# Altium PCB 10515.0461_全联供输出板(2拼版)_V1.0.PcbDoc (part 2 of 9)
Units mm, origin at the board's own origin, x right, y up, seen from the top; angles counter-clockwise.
Board outline 283.88 x 134.8 mm, 2 copper layers (Top Layer, Bottom Layer); 298 components, 0 nets, 1264 pads, 970 vias.
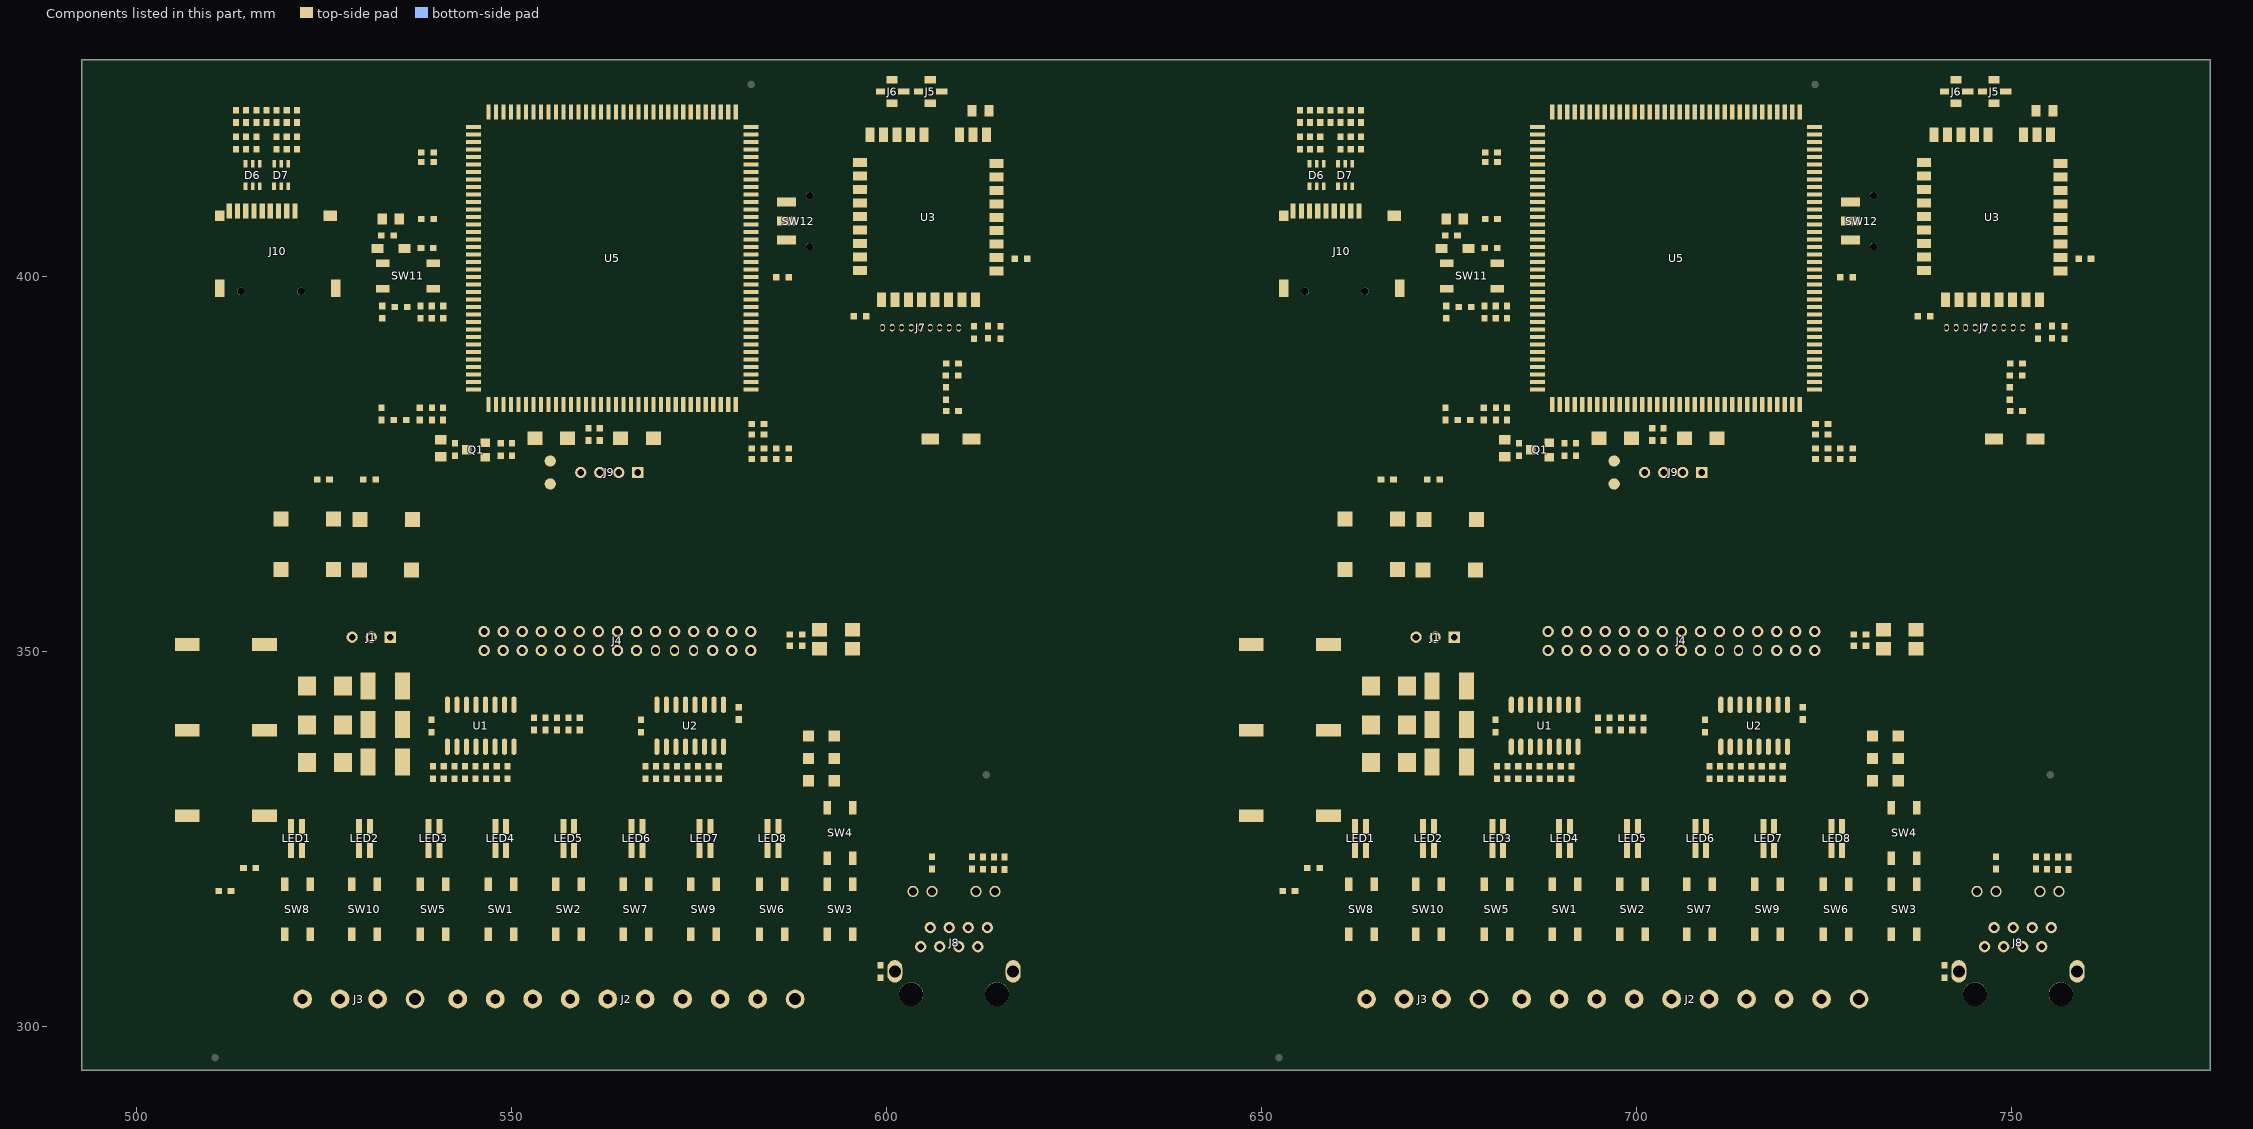
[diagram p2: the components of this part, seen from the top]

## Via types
v1: diameter 0.7, hole 0.4, Top Layer to Bottom Layer, tented both sides, 970 vias

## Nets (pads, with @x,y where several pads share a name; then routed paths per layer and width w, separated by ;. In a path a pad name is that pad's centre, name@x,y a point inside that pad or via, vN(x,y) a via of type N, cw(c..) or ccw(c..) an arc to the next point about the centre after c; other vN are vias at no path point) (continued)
copper on no net: (continued)
  Top Layer w0.3: 512.154,409.49 ccw(c511.813,409.831) 512.296,409.831 ccw(c512.779,409.831) 512.437,409.49 ; 512.296,408.698 512.296,414.58 512.699,414.983 514.482,414.983 v1@514.482,415.867 ; 513.026,418.822 ccw(c512.588,419.26) 513.207,419.26 ccw(c513.826,419.26) 513.388,418.822 ; 513.026,420.288 cw(c512.588,419.85) 513.207,419.85 cw(c513.826,419.85) 513.388,420.288 ; 513.026,422.378 ccw(c512.588,422.816) 513.207,422.816 ccw(c513.826,422.816) 513.388,422.378 ; v1@513.066,419.414 cw(c512.724,419.072) 513.207,419.072 cw(c513.69,419.072) v1@513.348,419.414 ; v1@513.066,419.696 ccw(c512.724,420.038) 513.207,420.038 ccw(c513.69,420.038) v1@513.348,419.696 ; 513.207,416.952 515.916,416.952 518.626,416.952 521.335,416.952 521.525,416.952 521.97,416.507 v1(521.97,410.538) ; 513.207,418.603 513.207,420.508 ; 513.207,422.159 513.207,425.143 v1(513.461,425.397) ; 513.207,424.301 cw(c514.557,424.301) v1@513.602,425.256 ; 513.207,425.025 cw(c513.833,425.025) v1@513.39,425.468 ; 513.258,409.49 ccw(c512.917,409.831) 513.4,409.831 ccw(c513.882,409.831) 513.541,409.49 ; 513.388,416.77 cw(c513.826,416.332) 513.826,416.952 cw(c513.826,417.571) 513.388,417.133 ; 513.4,408.698 513.4,413.398 513.842,413.84 516.128,413.84 516.382,414.094 516.382,414.983 v1@516.382,415.872 ; v1@514.209,412.81 cw(c513.561,412.162) 514.477,412.162 ; v1@514.214,415.726 cw(c513.566,415.078) 514.482,415.078 ; 514.356,409.49 ccw(c514.015,409.831) 514.498,409.831 ccw(c514.98,409.831) 514.639,409.49 ; 514.38,416.77 ccw(c513.943,416.332) 513.943,416.952 ccw(c513.943,417.571) 514.38,417.133 ; 514.38,418.822 ccw(c513.943,419.26) 514.562,419.26 ccw(c515.181,419.26) 514.743,418.822 ; 514.38,420.288 cw(c513.943,419.85) 514.562,419.85 cw(c515.181,419.85) 514.743,420.288 ; 514.38,422.378 ccw(c513.84,422.918) 514.604,422.918 ; 514.406,411.662 cw(c514.186,411.442) 514.498,411.442 ; v1@514.42,419.414 cw(c514.079,419.072) 514.562,419.072 cw(c515.045,419.072) v1@514.703,419.414 ; v1@514.42,419.696 ccw(c514.079,420.038) 514.562,420.038 ccw(c515.045,420.038) v1@514.703,419.696 ; 514.477,411.983 v1@514.477,412.951 ; 514.498,408.698 514.498,411.835 ; 514.562,418.603 514.562,420.508 ; 514.604,422.201 514.604,423.407 514.604,426.286 515.196,426.878 562.272,426.878 v1(562.737,426.413) ; 514.604,422.713 ccw(c515.078,422.713) 514.743,422.378 ; 514.743,416.77 cw(c515.181,416.332) 515.181,416.952 cw(c515.181,417.571) 514.743,417.133 ; v1@514.971,406.742 ccw(c513.465,408.248) 515.594,408.248 ; v1@515.183,406.53 ccw(c514.19,407.523) 515.594,407.523 ; v1@515.186,415.726 cw(c514.591,415.131) 515.432,415.131 ; 515.395,406.318 ccw(c514.914,406.799) 515.594,406.799 ; 515.432,411.983 515.432,410.853 515.681,410.604 ; 515.432,414.983 v1@515.432,415.811 ; 515.453,407.907 cw(c515.111,407.565) 515.594,407.565 cw(c516.077,407.565) 515.736,407.907 ; 515.594,406.601 515.594,408.698 515.594,409.548 ; 515.735,416.77 ccw(c515.297,416.332) 515.297,416.952 ccw(c515.297,417.571) 515.735,417.133 ; 515.735,418.822 ccw(c515.297,419.26) 515.916,419.26 ccw(c516.535,419.26) 516.098,418.822 ; 515.735,420.288 cw(c515.297,419.85) 515.916,419.85 cw(c516.535,419.85) 516.098,420.288 ; 515.735,422.378 ccw(c515.297,422.816) 515.916,422.816 ccw(c516.535,422.816) 516.098,422.378 ; v1@515.775,419.414 cw(c515.433,419.072) 515.916,419.072 cw(c516.399,419.072) v1@516.058,419.414 ; v1@515.775,419.696 ccw(c515.433,420.038) 515.916,420.038 ccw(c516.399,420.038) v1@516.058,419.696 ; v1@515.904,410.489 ccw(c515.681,410.332) 515.681,410.604 ; v1@515.904,410.719 cw(c515.681,410.876) 515.681,410.604 ; 515.916,418.603 515.916,420.508 ; 515.916,422.159 515.916,425.947 516.293,426.324 561.556,426.324 562.865,425.015 562.865,421.91 ; v1@515.94,410.604 515.681,410.604 ; 516.098,416.77 cw(c516.535,416.332) 516.535,416.952 cw(c516.535,417.571) 516.098,417.133 ; v1@516.158,415.726 cw(c515.616,415.184) 516.382,415.184 ; 516.382,411.983 516.946,411.983 ; 516.551,409.49 ccw(c515.596,410.444) 516.946,410.444 ; 516.763,409.277 ccw(c516.321,409.72) 516.946,409.72 ; 516.946,408.698 516.946,411.983 ; 517.09,420.288 cw(c516.652,419.85) 517.271,419.85 cw(c517.89,419.85) 517.452,420.288 ; 517.09,422.378 ccw(c516.652,422.816) 517.271,422.816 ccw(c517.89,422.816) 517.452,422.378 ; v1@517.13,415.726 cw(c516.788,415.384) 517.271,415.384 cw(c517.754,415.384) v1@517.412,415.726 ; v1@517.13,418.045 ccw(c516.788,418.387) 517.271,418.387 ccw(c517.754,418.387) v1@517.412,418.045 ; v1(517.144,425.397) 517.517,425.77 560.713,425.77 561.865,424.618 561.865,421.91 ; v1@517.144,425.597 ccw(c517.144,426.08) 517.485,425.738 ccw(c517.827,425.397) v1@517.344,425.397 ; v1@517.271,415.872 517.271,412.308 516.946,411.983 ; v1(517.271,417.904) 517.271,420.508 ; 517.271,422.159 517.271,423.492 518.033,424.254 559.484,424.254 559.865,423.873 559.865,421.91 ; 517.652,408.837 v1@517.652,410.538 ; 517.652,409.815 cw(c518.568,409.815) v1@517.92,410.463 ; 517.652,410.167 ccw(c518.61,410.167) 517.933,409.49 ; v1@518.146,413.699 cw(c517.804,413.357) 518.287,413.357 cw(c518.77,413.357) v1@518.428,413.699 ; 518.216,411.662 cw(c517.432,410.878) 518.541,410.878 ; v1(518.287,413.84) 518.287,411.983 518.541,411.729 518.541,410.157 518.891,409.807 ; 518.428,411.874 cw(c518.157,411.603) 518.541,411.603 ; 518.444,416.77 ccw(c518.007,416.332) 518.007,416.952 ccw(c518.007,417.571) 518.444,417.133 ; 518.444,418.822 ccw(c518.007,419.26) 518.626,419.26 ccw(c519.245,419.26) 518.807,418.822 ; 518.444,420.288 cw(c518.007,419.85) 518.626,419.85 cw(c519.245,419.85) 518.807,420.288 ; 518.444,422.378 ccw(c518.007,422.816) 518.626,422.816 ccw(c519.245,422.816) 518.807,422.378 ; v1@518.484,419.414 cw(c518.143,419.072) 518.626,419.072 cw(c519.109,419.072) v1@518.767,419.414 ; v1@518.484,419.696 ccw(c518.143,420.038) 518.626,420.038 ccw(c519.109,420.038) v1@518.767,419.696 ; v1@518.484,423.266 cw(c518.143,422.924) 518.626,422.924 cw(c519.109,422.924) v1@518.767,423.266 ; 518.626,418.603 518.626,420.508 ; 518.626,422.159 v1(518.626,423.407) ; 518.754,409.495 ccw(c518.463,409.807) 518.891,409.807 ; 518.774,409.924 cw(c518.246,409.397) 518.99,409.341 ; 518.807,416.77 cw(c519.245,416.332) 519.245,416.952 cw(c519.245,417.571) 518.807,417.133 ; 518.891,408.698 518.891,409.807 ; 519.027,409.495 cw(c519.318,409.807) 518.891,409.807 ; v1@519.035,413.346 ccw(c518.534,413.847) 519.242,413.847 ; v1(519.049,425.016) 560.197,425.016 560.865,424.348 560.865,421.91 ; v1@519.19,424.875 cw(c519.532,424.533) 519.532,425.016 cw(c519.532,425.499) v1@519.19,425.157 ; v1@519.242,410.604 519.242,411.983 ; 519.242,411.168 ccw(c519.933,411.168) v1@519.444,410.679 ; v1@519.242,413.271 519.242,414.983 ; 519.799,416.77 ccw(c519.361,416.332) 519.361,416.952 ccw(c519.361,417.571) 519.799,417.133 ; 519.799,418.822 ccw(c519.361,419.26) 519.98,419.26 ccw(c520.599,419.26) 520.162,418.822 ; 519.799,420.288 cw(c519.361,419.85) 519.98,419.85 cw(c520.599,419.85) 520.162,420.288 ; 519.799,422.378 ccw(c519.361,422.816) 519.98,422.816 ccw(c520.599,422.816) 520.162,422.378 ; v1@519.839,419.414 cw(c519.497,419.072) 519.98,419.072 cw(c520.463,419.072) v1@520.122,419.414 ; v1@519.839,419.696 ccw(c519.497,420.038) 519.98,420.038 ccw(c520.463,420.038) v1@520.122,419.696 ; v1@519.839,423.308 cw(c519.497,422.967) 519.98,422.967 cw(c520.463,422.967) v1@520.122,423.308 ; 519.846,409.488 ccw(c519.009,410.324) 520.192,410.324 ; 519.98,418.603 519.98,420.508 ; 519.98,422.159 v1(519.98,423.45) ; 519.987,408.696 519.987,409.444 520.192,409.649 520.192,411.983 v1(520.192,413.586) ; v1@520.051,413.445 cw(c519.709,413.103) 520.192,413.103 cw(c520.675,413.103) v1@520.333,413.445 ; v1@520.051,415.731 cw(c519.709,415.389) 520.192,415.389 cw(c520.675,415.389) v1@520.333,415.731 ; 520.162,416.77 cw(c520.599,416.332) 520.599,416.952 cw(c520.599,417.571) 520.162,417.133 ; 520.192,414.633 cw(c520.192,413.788) 520.789,414.386 ; v1(520.192,415.872) 520.192,414.983 521.087,414.088 521.087,408.698 ; 520.396,327.393 ccw(c519.969,327.82) 520.573,327.82 ccw(c521.177,327.82) 520.75,327.393 ; 520.573,326.235 520.573,330.782 521.265,331.474 539.172,331.474 539.496,331.798 539.496,333.005 ; v1(520.573,427.683) 520.692,427.564 562.729,427.564 563.865,426.428 563.865,421.91 ; v1@520.714,427.824 ccw(c521.343,428.453) 521.343,427.564 ; 520.945,409.49 ccw(c520.604,409.831) 521.087,409.831 ccw(c521.569,409.831) 521.228,409.49 ; 521.154,416.77 ccw(c520.716,416.332) 520.716,416.952 ccw(c520.716,417.571) 521.154,417.133 ; 521.154,418.822 ccw(c520.716,419.26) 521.335,419.26 ccw(c521.954,419.26) 521.516,418.822 ; 521.154,420.288 cw(c520.716,419.85) 521.335,419.85 cw(c521.954,419.85) 521.516,420.288 ; 521.154,422.378 ccw(c520.716,422.816) 521.335,422.816 ccw(c521.954,422.816) 521.516,422.378 ; v1@521.194,419.414 cw(c520.852,419.072) 521.335,419.072 cw(c521.818,419.072) v1@521.476,419.414 ; v1@521.194,419.696 ccw(c520.852,420.038) 521.335,420.038 ccw(c521.818,420.038) v1@521.476,419.696 ; v1@521.194,423.351 cw(c520.852,423.009) 521.335,423.009 cw(c521.818,423.009) v1@521.476,423.351 ; 521.335,418.603 521.335,420.508 ; 521.335,422.159 v1(521.335,423.492) ; v1@521.829,410.679 ccw(c521.487,411.021) 521.97,411.021 ccw(c522.453,411.021) v1@522.111,410.679 ; 521.856,327.368 ccw(c521.429,327.795) 522.033,327.795 ccw(c522.637,327.795) 522.21,327.368 ; v1(521.97,428.318) 563.499,428.318 564.865,426.952 564.865,421.91 ; 522.033,326.21 522.033,330.21 522.743,330.92 540.65,330.92 540.911,331.181 540.911,333.005 ; 523.086,312.243 v1(526.923,312.243) ; 523.333,311.995 cw(c523.931,311.398) 523.931,312.243 cw(c523.931,313.088) 523.333,312.49 ; v1@526.782,312.101 ccw(c526.44,311.76) 526.44,312.243 ccw(c526.44,312.726) v1@526.782,312.384 ; 528.125,309.192 528.633,309.7 ; 528.385,311.595 cw(c527.788,310.998) 528.633,310.998 cw(c529.478,310.998) 528.88,311.595 ; 528.385,319.59 ccw(c527.788,320.188) 528.633,320.188 ccw(c529.478,320.188) 528.88,319.59 ; v1@528.492,320.286 cw(c528.15,319.944) 528.633,319.944 cw(c529.116,319.944) v1@528.774,320.286 ; 528.633,309.26 528.633,309.7 ; 528.633,312.243 528.633,309.7 ; 528.633,318.943 v1(528.633,320.427) ; 529.082,309.251 528.633,309.7 ; 529.468,327.393 ccw(c529.041,327.82) 529.644,327.82 ccw(c530.248,327.82) 529.821,327.393 ; 529.644,326.235 529.644,329.82 530.19,330.366 542.001,330.366 542.326,330.691 542.326,333.005 ; 530.928,327.368 ccw(c530.501,327.795) 531.104,327.795 ccw(c531.708,327.795) 531.281,327.368 ; 531.104,326.21 531.104,329.248 531.668,329.812 543.352,329.812 543.741,330.201 543.741,333.005 ; 531.785,319.59 ccw(c531.188,320.188) 532.033,320.188 ccw(c532.878,320.188) 532.28,319.59 ; 532.033,318.943 532.033,321.541 532.476,321.984 550.129,321.984 550.488,322.343 550.488,334.916 551.688,336.116 561.086,336.116 561.459,336.489 561.459,346.608 561.546,346.695 561.546,350.086 ; v1(533.146,321.003) 533.573,321.43 550.358,321.43 551.042,322.114 551.042,334.2 552.069,335.227 561.467,335.227 562.013,335.773 562.013,346.378 562.864,347.229 562.864,351.404 564.086,352.626 ; v1@533.146,321.203 ccw(c533.146,321.686) 533.487,321.344 ccw(c533.829,321.003) v1@533.346,321.003 ; v1(533.4,312.243) 537.783,312.243 ; v1@533.541,312.101 cw(c533.883,311.76) 533.883,312.243 cw(c533.883,312.726) v1@533.541,312.384 ; 537.536,311.995 ccw(c536.938,311.398) 536.938,312.243 ccw(c536.938,313.088) 537.536,312.49 ; 537.689,403.938 ccw(c537.251,404.376) 537.87,404.376 ccw(c538.489,404.376) 538.052,403.938 ; 537.727,415.056 cw(c537.289,414.618) 537.909,414.618 cw(c538.528,414.618) 538.09,415.056 ; 537.727,415.418 ccw(c537.289,415.856) 537.909,415.856 ccw(c538.528,415.856) 538.09,415.418 ; 537.727,416.326 cw(c537.289,415.888) 537.909,415.888 cw(c538.528,415.888) 538.09,416.326 ; 537.783,319.544 539.115,320.876 550.672,320.876 551.596,321.8 551.596,333.484 552.577,334.465 561.848,334.465 562.567,335.184 562.567,346.149 564.086,347.668 564.086,350.086 ; 537.783,319.693 ccw(c537.783,320.051) 538.037,319.798 ; 537.87,403.757 537.87,405.61 538.17,405.91 544.865,405.91 ; 537.909,416.507 537.909,414.158 538.226,413.84 540.766,413.84 541.836,414.91 544.865,414.91 546.427,414.91 546.735,414.602 546.735,385.91 ; 538.133,319.343 cw(c539.465,319.343) 538.523,320.284 ; 538.716,326.616 538.716,328.859 539.115,329.258 544.703,329.258 545.157,329.712 545.157,333.005 ; 538.716,328.17 ccw(c539.815,328.17) 539.038,327.393 ; 539.315,332.785 cw(c538.877,332.347) 539.496,332.347 cw(c540.115,332.347) 539.677,332.785 ; 539.336,334.894 ccw(c539.069,335.227) 539.496,335.227 ; 539.34,403.938 ccw(c538.902,404.376) 539.521,404.376 ccw(c540.14,404.376) 539.703,403.938 ; 539.452,334.694 cw(c540.635,334.694) 539.799,335.53 ; 539.496,334.656 539.496,335.227 ; 539.521,403.757 539.521,404.467 539.964,404.91 544.865,404.91 546.648,404.91 ; 539.559,407.617 540.267,406.91 544.865,406.91 ; 539.559,415.237 540.639,415.237 541.312,415.91 544.865,415.91 ; 539.559,416.507 539.962,416.91 544.865,416.91 ; 539.567,416.538 cw(c540.465,415.639) 540.465,416.91 ; 539.598,407.361 cw(c539.598,406.834) 539.97,407.206 ; 539.656,334.894 cw(c539.923,335.227) 539.496,335.227 ; 539.752,334.694 cw(c541.659,334.694) 540.311,336.042 ; 539.779,415.056 cw(c540.217,414.618) 540.217,415.237 cw(c540.217,415.856) 539.779,415.418 ; 539.779,416.326 cw(c541.19,414.915) 541.19,416.91 ; 539.854,407.617 ccw(c540.565,407.617) 540.062,407.114 ; 540.176,326.591 540.176,328.287 540.512,328.623 546.1,328.623 546.572,329.095 546.572,333.005 ; 540.176,328.145 ccw(c541.275,328.145) 540.498,327.368 ; 540.73,332.785 cw(c540.292,332.347) 540.911,332.347 cw(c541.53,332.347) 541.092,332.785 ; 540.73,334.875 ccw(c539.11,336.495) 541.401,336.495 ; 540.911,334.656 541.401,335.145 ; 540.916,334.95 ccw(c540.929,335.617) 541.401,335.145 ; 540.942,334.663 ccw(c539.834,335.771) 541.401,335.771 ; 541.154,334.451 ccw(c540.558,335.047) 541.401,335.047 ; 541.168,334.694 cw(c541.695,334.694) 541.322,335.066 ; 541.183,312.243 546.832,312.243 ; 541.26,336.368 cw(c540.918,336.026) 541.401,336.026 cw(c541.884,336.026) 541.542,336.368 ; 541.401,337.259 541.401,335.145 ; 541.431,311.995 cw(c542.028,311.398) 542.028,312.243 cw(c542.028,313.088) 541.431,312.49 ; 542.145,332.785 cw(c541.707,332.347) 542.326,332.347 cw(c542.945,332.347) 542.508,332.785 ; 542.145,334.875 ccw(c540.875,336.145) 542.671,336.145 ; 542.326,334.656 542.671,335 542.671,337.259 ; 542.357,334.663 ccw(c541.599,335.421) 542.671,335.421 ; 542.53,336.368 cw(c542.188,336.026) 542.671,336.026 cw(c543.154,336.026) 542.812,336.368 ; 542.53,341.956 cw(c542.188,341.614) 542.671,341.614 cw(c543.154,341.614) 542.812,341.956 ; 542.671,342.847 542.671,340.561 540.385,338.275 540.385,336.116 539.496,335.227 ; 543.56,332.785 cw(c543.122,332.347) 543.741,332.347 cw(c544.36,332.347) 543.923,332.785 ; 543.56,334.875 ccw(c542.641,335.794) 543.941,335.794 ; 543.772,334.663 ccw(c543.365,335.07) 543.941,335.07 ; 543.8,336.368 cw(c543.458,336.026) 543.941,336.026 cw(c544.424,336.026) 544.082,336.368 ; 543.941,334.855 543.941,337.259 ; 544.052,404.822 ccw(c543.838,404.608) 543.838,404.91 ccw(c543.838,405.212) 544.052,404.998 ; 544.052,405.822 ccw(c543.838,405.608) 543.838,405.91 ccw(c543.838,406.212) 544.052,405.998 ; 544.052,406.822 ccw(c543.838,406.608) 543.838,406.91 ccw(c543.838,407.212) 544.052,406.998 ; 544.052,414.822 ccw(c543.838,414.608) 543.838,414.91 ccw(c543.838,415.212) 544.052,414.998 ; 544.052,415.822 ccw(c543.838,415.608) 543.838,415.91 ccw(c543.838,416.212) 544.052,415.998 ; 544.052,416.822 ccw(c543.838,416.608) 543.838,416.91 ccw(c543.838,417.212) 544.052,416.998 ; v1@544.576,382.471 544.576,383.36 ; 544.576,383.233 544.576,383.36 ; 544.576,383.911 cw(c545.864,383.911) 544.953,384.822 ccw(c545.167,384.608) 544.865,384.608 ccw(c544.563,384.608) 544.777,384.822 ; 544.576,384.635 cw(c545.14,384.635) 544.741,385.034 ; 544.636,384.69 cw(c544.865,384.461) 544.865,384.785 ; v1@544.647,382.527 ccw(c544.12,383.054) 544.865,383.054 ; 544.658,384.712 ccw(c544.46,384.91) 544.74,384.91 ; v1@544.703,382.471 544.865,382.633 544.865,384.91 ; v1@544.717,382.739 cw(c545.059,383.081) 544.576,383.081 cw(c544.093,383.081) 544.435,382.739 ccw(c543.395,383.779) 544.865,383.779 ; 544.865,385.91 546.735,385.91 ; 544.865,388.91 546.697,388.91 ; 544.865,391.91 546.694,391.91 ; 544.865,394.91 546.728,394.91 ; 544.865,397.91 546.663,397.91 ; 544.975,332.785 cw(c544.538,332.347) 545.157,332.347 cw(c545.776,332.347) 545.338,332.785 ; 544.975,334.875 ccw(c544.406,335.444) 545.211,335.444 ; 545.07,336.368 cw(c544.728,336.026) 545.211,336.026 cw(c545.694,336.026) 545.352,336.368 ; 545.211,334.71 545.211,337.259 ; 545.211,335.181 ccw(c545.644,335.181) 545.338,334.875 ; 545.678,384.822 cw(c545.892,384.608) 545.892,384.91 cw(c545.892,385.212) 545.678,384.998 ; 545.678,385.822 cw(c545.892,385.608) 545.892,385.91 cw(c545.892,386.212) 545.678,385.998 ; 545.678,388.822 cw(c545.892,388.608) 545.892,388.91 cw(c545.892,389.212) 545.678,388.998 ; 545.678,391.822 cw(c545.892,391.608) 545.892,391.91 cw(c545.892,392.212) 545.678,391.998 ; 545.678,394.822 cw(c545.892,394.608) 545.892,394.91 cw(c545.892,395.212) 545.678,394.998 ; 545.678,397.822 cw(c545.892,397.608) 545.892,397.91 cw(c545.892,398.212) 545.678,397.998 ; 545.678,404.822 cw(c545.892,404.608) 545.892,404.91 cw(c545.892,405.212) 545.678,404.998 ; 545.678,414.822 cw(c545.892,414.608) 545.892,414.91 cw(c545.892,415.212) 545.678,414.998 ; 546.34,336.368 cw(c545.998,336.026) 546.481,336.026 cw(c546.964,336.026) 546.622,336.368 ; 546.34,343.738 ccw(c545.998,344.08) 546.481,344.08 ccw(c546.964,344.08) 546.622,343.738 ; v1@546.34,344.23 cw(c545.998,343.888) 546.481,343.888 cw(c546.964,343.888) v1@546.622,344.23 ; 546.354,380.82 546.862,381.328 546.862,381.455 ; 546.39,332.785 cw(c545.953,332.347) 546.572,332.347 cw(c547.191,332.347) 546.753,332.785 ; 546.39,334.875 ccw(c546.172,335.094) 546.481,335.094 ; 546.481,334.746 546.481,337.259 ; 546.481,335.532 ccw(c547.41,335.532) 546.753,334.875 ; 546.481,342.847 v1(546.481,344.371) ; 546.585,311.995 ccw(c545.987,311.398) 545.987,312.243 ccw(c545.987,313.088) 546.585,312.49 ; 546.777,382.097 cw(c546.57,381.89) 546.862,381.89 ; 546.832,318.943 546.832,319.322 547.832,320.322 551.007,320.322 552.15,321.465 552.15,333.149 552.577,333.576 556.26,333.576 561.975,333.576 563.121,334.722 563.121,345.919 565.252,348.05 565.252,351.252 566.626,352.626 ; 546.832,319.693 ccw(c546.832,320.588) 547.465,319.955 ; 546.862,381.201 546.862,381.455 ; 546.862,381.876 cw(c547.174,381.876) 546.953,382.097 ; 546.865,382.91 546.862,382.907 546.862,381.455 ; 546.875,381.214 547.865,381.214 ; 547.182,319.343 cw(c547.977,319.343) 547.415,319.905 ; 547.611,327.393 ccw(c546.702,328.301) 547.987,328.301 ; 547.61,336.368 cw(c547.268,336.026) 547.751,336.026 cw(c548.234,336.026) 547.892,336.368 ; 547.61,343.738 ccw(c547.268,344.08) 547.751,344.08 ccw(c548.234,344.08) 547.892,343.738 ; 547.751,334.891 547.751,337.259 ; 547.751,335.158 ccw(c548.451,335.158) 547.956,334.663 ; 547.751,335.882 ccw(c549.175,335.882) 548.168,334.875 ; 547.751,342.847 547.751,344.752 v1(548.259,345.26) ; 547.787,327.317 547.787,326.616 547.987,326.816 547.987,333.005 ; 547.806,332.785 cw(c547.368,332.347) 547.987,332.347 cw(c548.606,332.347) 548.168,332.785 ; 547.823,327.181 ccw(c547.426,327.577) 547.987,327.577 ; 547.865,380.82 547.963,380.722 548.865,380.722 548.865,382.91 ; v1@548.059,345.26 cw(c547.576,345.26) 547.918,344.919 cw(c548.259,344.577) v1@548.259,345.06 ; v1@548.626,385.769 ccw(c548.284,385.427) 548.284,385.91 ccw(c548.284,386.393) v1@548.626,386.051 ; 548.777,382.097 cw(c548.563,381.883) 548.865,381.883 cw(c549.167,381.883) 548.953,382.097 ; 548.88,336.368 cw(c548.538,336.026) 549.021,336.026 cw(c549.504,336.026) 549.162,336.368 ; v1@548.908,385.769 cw(c549.25,385.427) 549.25,385.91 cw(c549.25,386.393) v1@548.908,386.051 ; 549.021,335.036 549.021,337.259 ; 549.021,335.508 ccw(c550.217,335.508) 549.371,334.663 ; 549.021,336.232 ccw(c550.941,336.232) 549.583,334.875 ; 549.071,327.368 ccw(c548.27,328.168) 549.402,328.168 ; 549.221,332.785 cw(c548.783,332.347) 549.402,332.347 cw(c550.021,332.347) 549.583,332.785 ; 549.247,327.254 549.247,326.591 549.402,326.746 549.402,333.005 ; 550.232,312.243 555.881,312.243 555.881,311.73 ; 550.232,318.531 552.704,321.003 552.704,332.433 553.085,332.814 562.483,332.814 563.675,334.006 563.675,345.69 566.626,348.641 566.626,350.086 ; 550.48,311.995 cw(c551.077,311.398) 551.077,312.243 cw(c551.077,313.088) 550.48,312.49 ; v1@551.547,313.143 ccw(c551.205,313.485) 551.688,313.485 ccw(c552.171,313.485) v1@551.829,313.143 ; v1(551.688,313.002) 551.688,319.204 553.258,320.774 553.258,331.463 553.855,332.06 563.126,332.06 564.229,333.163 564.229,345.461 567.817,349.049 567.817,353.515 567.428,353.904 562.618,353.904 ; v1@552.436,313.651 ccw(c552.094,313.993) 552.577,313.993 ccw(c553.06,313.993) v1@552.718,313.651 ; v1@552.577,313.637 552.577,319.309 553.863,320.595 553.863,330.925 554.444,331.506 563.588,331.506 564.783,332.701 564.783,345.231 567.398,347.846 571.292,347.846 571.706,348.26 571.706,350.086 ; 552.777,339.262 cw(c552.339,338.824) 552.958,338.824 cw(c553.577,338.824) 553.139,339.262 ; 552.958,336.116 552.958,339.482 ; 553.06,378.407 553.06,378.661 ; v1@553.452,313.143 ccw(c553.11,313.485) 553.593,313.485 ccw(c554.076,313.485) v1@553.734,313.143 ; v1@553.452,385.769 ccw(c553.11,385.427) 553.11,385.91 ccw(c553.11,386.393) v1@553.452,386.051 ; v1(553.593,313.002) 553.593,319.542 554.482,320.431 554.482,330.346 555.088,330.952 564.05,330.952 565.337,332.239 565.337,345.002 567.627,347.292 577.469,347.292 578.104,347.927 578.104,351.308 576.786,352.626 ; v1@553.734,385.769 cw(c554.076,385.427) 554.076,385.91 cw(c554.076,386.393) v1@553.734,386.051 ; 554.301,339.262 cw(c553.863,338.824) 554.482,338.824 cw(c555.101,338.824) 554.663,339.262 ; v1@554.341,313.651 ccw(c553.999,313.993) 554.482,313.993 ccw(c554.965,313.993) v1@554.623,313.651 ; v1@554.341,335.086 ccw(c553.999,334.744) 553.999,335.227 ccw(c553.999,335.71) v1@554.341,335.368 ; v1@554.341,338.416 ccw(c553.999,338.758) 554.482,338.758 ccw(c554.965,338.758) v1@554.623,338.416 ; v1@554.482,313.637 554.482,319.606 555.102,320.226 555.102,329.57 555.93,330.398 564.893,330.398 565.891,331.396 565.891,344.772 567.857,346.738 578.439,346.738 579.326,347.625 579.326,350.086 ; v1(554.482,338.275) 554.482,339.482 ; v1@554.623,335.086 cw(c554.965,334.744) 554.965,335.227 cw(c554.965,335.71) v1@554.623,335.368 ; 555.117,372.438 561.467,372.438 561.721,372.692 ; 555.117,375.359 556.895,375.359 557.428,375.892 557.428,378.09 ; 555.329,372.099 cw(c556.148,371.28) 556.148,372.438 ; 555.541,371.887 cw(c556.872,370.556) 556.872,372.438 ; 555.541,372.735 ccw(c556.259,373.453) 556.259,372.438 ; 555.541,374.935 cw(c556.566,373.91) 556.566,375.359 cw(c556.566,376.808) 555.541,375.783 ; 555.633,311.995 ccw(c555.036,311.398) 555.036,312.243 ccw(c555.036,313.088) 555.633,312.49 ; 555.825,339.262 cw(c555.387,338.824) 556.006,338.824 cw(c556.625,338.824) 556.187,339.262 ; v1@555.865,334.324 ccw(c555.523,333.982) 555.523,334.465 ccw(c555.523,334.948) v1@555.865,334.606 ; v1@555.865,338.416 ccw(c555.523,338.758) 556.006,338.758 ccw(c556.489,338.758) v1@556.147,338.416 ; 555.881,318.943 555.881,319.35 ; v1(556.006,338.275) 556.006,339.482 ; v1@556.147,334.324 cw(c556.489,333.982) 556.489,334.465 cw(c556.489,334.948) v1@556.147,334.606 ; 556.466,352.626 559.006,352.626 ; 556.682,327.393 ccw(c556.255,327.82) 556.859,327.82 ccw(c557.462,327.82) 557.035,327.393 ; 556.725,385.91 ccw(c556.725,386.489) v1@557.135,386.08 ; 556.859,326.235 556.859,326.616 556.859,329.603 557.1,329.844 566.879,329.844 567.817,330.782 567.817,333.005 ; 556.861,385.91 cw(c556.861,385.523) v1@557.135,385.797 ; v1(556.895,314.272) 558.8,314.272 ; 556.898,377.877 cw(c555.617,376.596) 557.428,376.596 cw(c559.239,376.596) 557.958,377.877 ; 556.899,352.193 cw(c557.943,351.149) 557.943,352.626 cw(c557.943,354.104) 556.899,353.059 ; v1@557.036,314.131 cw(c557.378,313.789) 557.378,314.272 cw(c557.378,314.755) v1@557.036,314.413 ; 557.11,378.089 cw(c556.342,377.321) 557.428,377.321 cw(c558.514,377.321) 557.746,378.089 ; 557.349,339.262 cw(c556.911,338.824) 557.53,338.824 cw(c558.149,338.824) 557.711,339.262 ; v1@557.389,333.435 ccw(c557.047,333.093) 557.047,333.576 ccw(c557.047,334.059) v1@557.389,333.717 ; v1@557.389,338.416 ccw(c557.047,338.758) 557.53,338.758 ccw(c558.013,338.758) v1@557.671,338.416 ; v1@557.417,385.797 cw(c557.691,385.523) 557.691,385.91 ; v1@557.417,386.08 ccw(c557.827,386.489) 557.827,385.91 ; v1(557.53,338.275) 557.53,339.482 ; v1@557.671,333.435 cw(c558.013,333.093) 558.013,333.576 cw(c558.013,334.059) v1@557.671,333.717 ; 558.142,327.368 ccw(c557.715,327.795) 558.319,327.795 ccw(c558.922,327.795) 558.495,327.368 ; 558.319,326.21 558.319,326.591 558.319,329.071 558.538,329.29 568.484,329.29 569.214,330.02 569.214,333.005 ; 558.573,352.193 ccw(c557.528,351.149) 557.528,352.626 ccw(c557.528,354.104) 558.573,353.059 ; 558.777,421.097 cw(c558.563,420.883) 558.865,420.883 cw(c559.167,420.883) 558.953,421.097 ; 558.865,421.91 558.865,418.347 559.302,417.91 577.865,417.91 ; 558.873,339.262 cw(c558.435,338.824) 559.054,338.824 cw(c559.673,338.824) 559.235,339.262 ; v1@558.913,332.673 ccw(c558.571,332.331) 558.571,332.814 ccw(c558.571,333.297) v1@558.913,332.955 ; v1@558.913,338.416 ccw(c558.571,338.758) 559.054,338.758 ccw(c559.537,338.758) v1@559.195,338.416 ; v1(559.054,338.275) 559.054,339.482 ; v1@559.195,332.673 cw(c559.537,332.331) 559.537,332.814 cw(c559.537,333.297) v1@559.195,332.955 ; 559.281,313.891 558.9,314.272 ; 559.281,314.272 558.8,314.272 ; 559.281,314.653 558.9,314.272 ; 559.281,318.943 559.281,319.325 560.36,320.404 572.861,320.404 573.877,319.388 573.877,318.943 ; 559.281,319.693 ccw(c559.281,320.581) 559.909,319.953 ; 559.631,319.343 cw(c560.432,319.343) 559.866,319.91 ; 559.777,383.723 ccw(c559.563,383.937) 559.865,383.937 ccw(c560.167,383.937) 559.953,383.723 ; 559.777,422.723 ccw(c559.563,422.937) 559.865,422.937 ccw(c560.167,422.937) 559.953,422.723 ; 559.79,384.91 544.865,384.91 ; 559.865,382.91 559.865,385.861 ; 560.016,377.87 cw(c559.578,377.432) 560.197,377.432 cw(c560.816,377.432) 560.378,377.87 ; 560.197,375.994 560.197,378.09 ; 560.197,379.741 560.865,380.409 560.865,382.91 ; 560.197,380.035 ccw(c560.197,380.746) 560.7,380.243 ; 560.453,379.779 cw(c560.98,379.779) 560.608,380.151 ; 560.777,382.097 cw(c560.563,381.883) 560.865,381.883 cw(c561.167,381.883) 560.953,382.097 ; 560.777,422.723 ccw(c560.563,422.937) 560.865,422.937 ccw(c561.167,422.937) 560.953,422.723 ; 561.113,349.653 cw(c560.068,348.609) 561.546,348.609 cw(c563.023,348.609) 561.979,349.653 ; 561.38,373.341 cw(c560.932,372.692) 561.721,372.692 ; 561.54,377.87 cw(c561.102,377.432) 561.721,377.432 cw(c562.34,377.432) 561.902,377.87 ; 561.54,379.96 ccw(c560.754,380.745) 561.865,380.745 ; 561.546,352.626 561.546,352.832 562.618,353.904 ; 561.546,353.238 ccw(c561.546,354.218) 562.239,353.525 ; 561.777,382.097 cw(c561.563,381.883) 561.865,381.883 cw(c562.167,381.883) 561.953,382.097 ; 561.777,422.723 ccw(c561.563,422.937) 561.865,422.937 ccw(c562.167,422.937) 561.953,422.723 ; 561.813,378.09 ccw(c561.813,380.984) 563.86,378.937 ; 561.857,352.648 cw(c562.872,352.719) 562.153,353.439 ; 561.865,379.885 561.865,382.91 ; 561.902,377.908 cw(c562.34,377.47) 562.34,378.09 cw(c562.34,378.709) 561.902,378.271 ; 562.062,373.341 ccw(c562.51,372.692) 561.721,372.692 ; 562.156,352.669 cw(c563.741,352.78) 562.618,353.904 ; 562.537,378.09 ccw(c562.537,380.26) 564.072,378.725 ; v1@562.537,426.413 ccw(c562.054,426.413) 562.396,426.754 ccw(c562.737,427.096) v1@562.737,426.613 ; v1@562.724,384.742 cw(c562.382,384.4) 562.865,384.4 cw(c563.348,384.4) v1@563.006,384.742 ; 562.777,303.604 562.777,308.095 563.245,308.563 590.429,308.563 592.455,310.589 596.265,310.589 596.9,311.224 596.9,330.909 596.392,331.417 589.915,331.417 589.56,331.772 ; 562.777,383.723 ccw(c562.563,383.937) 562.865,383.937 ccw(c563.167,383.937) 562.953,383.723 ; 562.777,422.723 ccw(c562.563,422.937) 562.865,422.937 ccw(c563.167,422.937) 562.953,422.723 ; 562.865,382.91 v1(562.865,384.883) ; 563.261,378.09 ccw(c563.261,379.536) 564.284,378.513 ; 563.346,378.09 cw(c563.346,377.363) 563.86,377.877 ; 563.474,352.626 cw(c561.996,352.626) 563.041,351.581 cw(c564.086,350.536) 564.086,352.014 ; 563.653,349.653 cw(c562.608,348.609) 564.086,348.609 cw(c565.563,348.609) 564.519,349.653 ; 563.777,422.723 ccw(c563.563,422.937) 563.865,422.937 ccw(c564.167,422.937) 563.953,422.723 ; 564.172,378.09 561.721,378.09 561.721,373.835 561.721,372.692 ; 564.777,382.097 cw(c564.563,381.883) 564.865,381.883 cw(c565.167,381.883) 564.953,382.097 ; 564.777,422.723 ccw(c564.563,422.937) 564.865,422.937 ccw(c565.167,422.937) 564.953,422.723 ; 564.865,382.91 564.865,380.724 565.785,379.804 571.5,379.804 571.881,379.423 571.881,376.248 572.516,375.613 581.977,375.613 ; 565.753,327.393 ccw(c565.327,327.82) 565.93,327.82 ccw(c566.534,327.82) 566.107,327.393 ; 565.777,382.097 cw(c565.563,381.883) 565.865,381.883 cw(c566.167,381.883) 565.953,382.097 ; 565.777,421.097 cw(c565.563,420.883) 565.865,420.883 cw(c566.167,420.883) 565.953,421.097 ; 565.865,382.91 565.865,381.248 566.547,380.566 572.135,380.566 572.516,380.185 572.516,377.518 573.024,377.01 581.977,377.01 ; 565.865,417.99 565.865,421.91 ; 565.93,326.235 565.93,326.616 565.93,328.26 566.293,328.623 569.722,328.623 570.611,329.512 570.611,333.005 ; 565.966,417.91 ccw(c565.966,418.806) v1@566.6,418.172 ; 566.014,352.626 cw(c564.536,352.626) 565.581,351.581 cw(c566.626,350.536) 566.626,352.014 ; 566.2,349.646 cw(c565.226,348.641) 566.626,348.641 cw(c568.026,348.641) 567.052,349.646 ; 566.777,382.097 cw(c566.563,381.883) 566.865,381.883 cw(c567.167,381.883) 566.953,382.097 ; 566.865,382.91 566.865,381.518 567.182,381.201 573.024,381.201 573.278,380.947 573.278,378.28 573.659,377.899 v1(587.883,377.899) ; v1@566.883,418.172 ccw(c567.516,418.806) 567.516,417.91 ; 566.999,304.382 ccw(c565.121,306.26) 567.777,306.26 ccw(c570.433,306.26) 568.555,304.382 ; 567.211,304.17 ccw(c565.846,305.535) 567.777,305.535 ccw(c569.708,305.535) 568.343,304.17 ; 567.241,327.392 ccw(c567.021,327.688) 567.39,327.688 ; 567.344,327.171 cw(c567.832,327.38) 567.457,327.755 ; 567.39,326.21 567.39,326.591 567.39,327.688 ; 567.539,327.392 cw(c567.759,327.688) 567.39,327.688 ; 567.596,385.91 ccw(c567.596,388.093) v1@569.14,386.549 ; 567.62,327.289 cw(c568.273,327.567) 567.771,328.069 ; 567.636,332.785 cw(c567.198,332.347) 567.817,332.347 cw(c568.436,332.347) 567.998,332.785 ; 567.636,334.875 ccw(c566.278,336.232) 568.198,336.232 ; 567.777,303.604 567.777,307.715 568.071,308.009 590.658,308.009 592.684,310.035 596.494,310.035 597.454,310.995 597.454,332.154 596.896,332.712 592.989,332.712 ; 567.817,334.656 568.198,335.037 568.198,338.021 570.611,340.434 570.611,342.847 ; 567.848,334.663 ccw(c567.002,335.508) 568.198,335.508 ; 568.32,385.91 ccw(c568.32,387.369) v1@569.352,386.337 ; 568.777,383.723 ccw(c568.563,383.937) 568.865,383.937 ccw(c569.167,383.937) 568.953,383.723 ; 568.865,382.91 568.865,385.815 ; 568.998,386.125 ccw(c569.518,386.645) 569.518,385.91 ; 569.033,332.785 cw(c568.595,332.347) 569.214,332.347 cw(c569.833,332.347) 569.395,332.785 ; 569.033,334.875 ccw(c568.288,335.619) 569.341,335.619 ; 569.045,385.91 ccw(c569.045,386.645) 569.564,386.125 ; 569.2,336.368 cw(c568.858,336.026) 569.341,336.026 cw(c569.824,336.026) 569.482,336.368 ; v1@569.21,386.337 ccw(c570.242,387.369) 570.242,385.91 ; 569.341,334.783 569.341,337.259 ; v1@569.423,386.549 ccw(c570.966,388.093) 570.966,385.91 ; 570.43,332.785 cw(c569.992,332.347) 570.611,332.347 cw(c571.23,332.347) 570.792,332.785 ; 570.43,334.875 ccw(c569.992,335.313) 570.611,335.313 ccw(c571.23,335.313) 570.792,334.875 ; 570.47,336.368 cw(c570.128,336.026) 570.611,336.026 cw(c571.094,336.026) 570.752,336.368 ; 570.47,341.956 cw(c570.128,341.614) 570.611,341.614 cw(c571.094,341.614) 570.752,341.956 ; 570.611,334.656 570.611,337.259 ; 571.388,349.606 cw(c570.62,348.838) 571.706,348.838 cw(c572.792,348.838) 572.024,349.606 ; 571.74,336.368 cw(c571.398,336.026) 571.881,336.026 cw(c572.364,336.026) 572.022,336.368 ; 571.74,343.738 ccw(c571.398,344.08) 571.881,344.08 ccw(c572.364,344.08) 572.022,343.738 ; 571.827,332.785 cw(c571.389,332.347) 572.008,332.347 cw(c572.627,332.347) 572.189,332.785 ; 571.881,334.783 571.881,337.259 ; 571.881,335.619 ccw(c572.934,335.619) 572.189,334.875 ; 571.881,342.847 571.881,345.768 572.262,346.149 581.406,346.149 581.866,346.609 581.866,350.086 ; 572.008,333.005 572.008,328.623 571.454,328.069 567.771,328.069 ; 572.777,303.604 572.777,306.954 573.278,307.455 590.888,307.455 592.914,309.481 596.724,309.481 598.008,310.765 598.008,333.957 597.627,334.338 590.169,334.338 589.56,334.947 589.56,335.697 ; v1@572.883,354.136 cw(c572.541,353.794) 573.024,353.794 cw(c573.507,353.794) v1@573.165,354.136 ; v1@572.883,354.418 ccw(c572.541,354.76) 573.024,354.76 ccw(c573.507,354.76) v1@573.165,354.418 ; v1@572.883,354.771 cw(c572.541,354.429) 573.024,354.429 cw(c573.507,354.429) v1@573.165,354.771 ; 573.01,336.368 cw(c572.668,336.026) 573.151,336.026 cw(c573.634,336.026) 573.292,336.368 ; v1(573.024,354.912) 573.024,351.308 574.246,350.086 ; 573.151,334.91 573.151,337.259 ; 573.151,335.202 ccw(c573.913,335.202) 573.374,334.663 ; 573.151,335.926 ccw(c574.637,335.926) 573.586,334.875 ; 573.201,351.131 ccw(c574.246,352.176) 574.246,350.698 ; 573.224,332.785 cw(c572.786,332.347) 573.405,332.347 cw(c574.024,332.347) 573.586,332.785 ; 573.247,320.018 cw(c572.572,319.343) 573.527,319.343 ; 573.357,319.908 ccw(c573.877,320.428) 573.877,319.693 ; 573.405,333.005 573.405,328.496 573.849,328.052 574.865,328.052 575.002,327.915 575.002,326.616 ; 573.592,350.74 cw(c573.101,350.248) 573.796,350.248 ; 573.713,350.619 ccw(c574.246,351.151) 574.246,350.398 ; 573.777,382.097 cw(c573.563,381.883) 573.865,381.883 cw(c574.167,381.883) 573.953,382.097 ; 573.777,421.097 cw(c573.563,420.883) 573.865,420.883 cw(c574.167,420.883) 573.953,421.097 ; 573.813,353.059 ccw(c572.768,354.104) 574.246,354.104 ccw(c575.723,354.104) 574.679,353.059 ; 573.865,382.91 573.865,379.423 574.373,378.915 581.977,378.915 ; 573.865,417.958 573.865,421.91 ; 574.246,352.626 574.246,354.991 575.056,355.801 589.788,355.801 590.05,356.063 ; 574.28,336.368 cw(c573.938,336.026) 574.421,336.026 cw(c574.904,336.026) 574.562,336.368 ; 574.28,343.738 ccw(c573.938,344.08) 574.421,344.08 ccw(c574.904,344.08) 574.562,343.738 ; v1@574.28,344.103 cw(c573.938,343.761) 574.421,343.761 cw(c574.904,343.761) v1@574.562,344.103 ; 574.421,335.037 574.421,337.259 ; 574.421,335.508 ccw(c575.617,335.508) 574.771,334.663 ; 574.421,336.232 ccw(c576.341,336.232) 574.983,334.875 ; 574.421,342.847 v1(574.421,344.244) ; 574.621,332.785 cw(c574.183,332.347) 574.802,332.347 cw(c575.421,332.347) 574.983,332.785 ; 574.777,382.097 cw(c574.563,381.883) 574.865,381.883 cw(c575.167,381.883) 574.953,382.097 ; 574.802,333.005 574.802,329.893 574.802,328.732 574.929,328.605 575.844,328.605 576.462,327.988 576.462,326.21 ; 574.825,327.393 ccw(c574.398,327.82) 575.002,327.82 ccw(c575.605,327.82) 575.178,327.393 ; 574.865,382.91 574.865,380.63 575.183,380.312 581.977,380.312 ; 575.002,326.235 575.002,326.899 ; 575.55,336.368 cw(c575.208,336.026) 575.691,336.026 cw(c576.174,336.026) 575.832,336.368 ; 575.55,343.738 ccw(c575.208,344.08) 575.691,344.08 ccw(c576.174,344.08) 575.832,343.738 ; v1@575.55,345.119 cw(c575.208,344.777) 575.691,344.777 cw(c576.174,344.777) 575.832,345.119 cw(c576.174,344.777) 576.174,345.26 cw(c576.174,345.743) v1@575.832,345.401 ; 575.691,335.091 ccw(c576.596,335.091) 575.956,334.451 ; 575.691,335.815 ccw(c577.32,335.815) 576.168,334.663 ; 575.691,336.539 ccw(c578.044,336.539) 576.38,334.875 ; 575.691,337.259 575.691,335.164 576.199,334.656 ; 575.691,342.847 v1(575.691,345.26) 582.422,345.26 583.438,346.276 583.438,350.975 583.057,351.356 580.596,351.356 579.326,352.626 ; 575.71,335.144 ccw(c576.18,335.614) 576.194,334.95 ; 575.788,335.066 cw(c575.416,334.694) 575.943,334.694 ; 576.018,332.785 cw(c575.58,332.347) 576.199,332.347 cw(c576.818,332.347) 576.38,332.785 ; 576.174,350.086 ccw(c574.696,350.086) 575.741,351.131 ccw(c576.786,352.176) 576.786,350.698 ; 576.199,333.005 576.199,330.092 576.906,329.385 583.565,329.385 584.073,328.877 584.073,326.235 ; 576.285,327.368 ccw(c575.858,327.795) 576.462,327.795 ccw(c577.065,327.795) 576.638,327.368 ; 576.786,350.086 575.564,351.308 575.564,354.531 575.945,354.912 590.636,354.912 590.636,352.991 ; 576.786,352.014 cw(c576.786,350.536) 577.831,351.581 cw(c578.875,352.626) 577.398,352.626 ; 576.82,336.368 cw(c576.478,336.026) 576.961,336.026 cw(c577.444,336.026) 577.102,336.368 ; 576.961,337.259 576.961,335.608 ; 576.999,304.382 ccw(c575.121,306.26) 577.777,306.26 ccw(c580.433,306.26) 578.555,304.382 ; 577.211,304.17 ccw(c575.846,305.535) 577.777,305.535 ccw(c579.708,305.535) 578.343,304.17 ; 577.34,334.694 ccw(c576.046,334.694) 576.961,335.608 ; 577.415,332.785 cw(c576.977,332.347) 577.596,332.347 cw(c578.215,332.347) 577.777,332.785 ; 577.473,335.096 cw(c577.07,334.694) 577.64,334.694 ; 577.596,333.005 577.596,330.393 577.969,330.02 584.708,330.02 585.533,329.195 585.533,326.21 ; 577.596,334.656 577.596,334.973 576.961,335.608 ; 577.728,385.91 546.735,385.91 ; 577.777,383.723 ccw(c577.563,383.937) 577.865,383.937 ccw(c578.167,383.937) 577.953,383.723 ; 577.777,303.604 577.777,306.447 578.231,306.901 591.117,306.901 593.143,308.927 596.953,308.927 598.562,310.536 598.562,335.227 598.092,335.697 ; 577.865,382.91 577.865,417.91 ; 577.865,386.201 cw(c578.73,386.201) v1@578.118,386.813 ; 577.865,387.707 ccw(c578.73,387.707) v1@578.118,387.096 ; 577.865,412.31 cw(c579.164,412.31) v1@578.245,413.229 ; 577.865,413.035 cw(c578.44,413.035) v1@578.033,413.441 ; 577.865,413.706 ccw(c578.44,413.706) v1@578.033,413.299 ; 577.865,414.43 ccw(c579.164,414.43) v1@578.245,413.512 ; 577.905,399.91 581.865,399.91 585.24,399.91 ; 577.922,390.91 581.865,390.91 ; 577.966,384.91 581.865,384.91 ; 577.97,387.91 581.865,387.91 ; 578.015,408.91 581.865,408.91 ; 578.777,382.097 cw(c578.563,381.883) 578.865,381.883 cw(c579.167,381.883) 578.953,382.097 ; 578.865,382.91 578.865,381.583 579.12,381.328 596.519,381.328 597.432,380.415 597.432,338.886 597.916,338.402 603.123,338.402 603.504,338.021 603.504,317.955 ; 578.893,349.653 cw(c577.848,348.609) 579.326,348.609 cw(c580.803,348.609) 579.759,349.653 ; v1(579.12,344.498) 580.263,344.498 ; v1@579.261,344.357 cw(c579.603,344.015) 579.603,344.498 cw(c579.603,344.981) v1@579.261,344.639 ; 579.326,352.014 cw(c579.326,350.536) 580.371,351.581 cw(c581.415,352.626) 579.938,352.626 ; 579.865,382.91 579.865,382.107 597.264,382.107 597.986,381.385 597.986,339.348 598.297,339.037 606.298,339.037 606.552,338.783 v1(606.552,325.575) ; 579.953,382.273 ccw(c580.355,382.675) 580.355,382.107 ; 580.082,342.749 ccw(c579.644,343.187) 580.263,343.187 ccw(c580.882,343.187) 580.444,342.749 ; 580.199,340.815 v1(581.406,340.815) 581.406,343.482 581.914,343.99 585.216,343.99 585.788,344.562 585.788,349.485 586.769,350.467 ; 580.263,342.657 580.263,344.498 ; 580.444,340.659 cw(c580.821,340.283) 580.821,340.815 ; 580.444,341.022 ccw(c580.943,341.521) 580.943,340.815 ; 581.052,384.822 ccw(c580.838,384.608) 580.838,384.91 ccw(c580.838,385.212) 581.052,384.998 ; 581.052,387.822 ccw(c580.838,387.608) 580.838,387.91 ccw(c580.838,388.212) 581.052,387.998 ; 581.052,390.822 ccw(c580.838,390.608) 580.838,390.91 ccw(c580.838,391.212) 581.052,390.998 ; 581.052,399.822 ccw(c580.838,399.608) 580.838,399.91 ccw(c580.838,400.212) 581.052,399.998 ; 581.052,408.822 ccw(c580.838,408.608) 580.838,408.91 ccw(c580.838,409.212) 581.052,408.998 ; 581.052,417.822 ccw(c580.838,417.608) 580.838,417.91 ccw(c580.838,418.212) 581.052,417.998 ; v1@581.265,340.674 ccw(c580.923,340.332) 580.923,340.815 ccw(c580.923,341.298) 581.265,340.956 ccw(c580.923,341.298) 581.406,341.298 ccw(c581.889,341.298) v1@581.547,340.956 ; 581.433,349.653 cw(c580.388,348.609) 581.866,348.609 cw(c583.343,348.609) 582.299,349.653 ; 581.758,375.432 ccw(c581.32,374.994) 581.32,375.613 ccw(c581.32,376.232) 581.758,375.794 ; 581.758,376.829 ccw(c581.32,376.391) 581.32,377.01 ccw(c581.32,377.629) 581.758,377.191 ; 581.758,378.734 ccw(c581.32,378.296) 581.32,378.915 ccw(c581.32,379.534) 581.758,379.096 ; 581.758,380.131 ccw(c581.32,379.693) 581.32,380.312 ccw(c581.32,380.931) 581.758,380.493 ; 581.865,385.91 597.652,385.91 598.54,385.022 598.54,341.035 599.314,340.261 600.837,340.261 601.137,340.261 601.737,340.261 601.956,340.261 602.256,340.261 602.856,340.261 603.456,340.261 603.456,339.661 604.056,339.661 604.056,340.261 606.171,340.261 608.884,340.261 609.173,339.972 609.173,315.969 609.646,315.496 611.813,315.496 612.144,315.165 612.144,310.585 ; 581.865,386.91 598.557,386.91 599.094,386.373 599.094,341.301 599.58,340.815 601.345,340.815 601.645,340.815 602.245,340.815 602.556,340.815 602.856,340.815 603.456,340.815 603.456,341.415 604.056,341.415 604.056,340.815 604.656,340.815 604.656,341.415 605.256,341.415 605.256,340.815 605.917,340.815 609.219,340.815 609.727,340.307 609.727,316.812 610.362,316.177 612.648,316.177 613.414,315.411 613.414,313.125 ; 581.865,388.91 598.589,388.91 599.648,387.851 599.648,342.639 600.202,342.085 607.06,342.085 v1(607.568,341.577) ; 581.865,389.91 599.24,389.91 600.202,388.948 600.202,343.482 600.71,342.974 601.853,342.974 602.153,342.974 602.153,343.65 602.753,343.65 602.753,342.974 604.139,342.974 605.79,342.974 607.568,342.974 v1(608.33,342.212) ; 581.865,406.91 584.145,406.91 584.454,406.601 584.454,405.204 584.835,404.823 586.613,404.823 ; 581.865,407.91 583.985,407.91 584.454,408.379 584.454,409.522 584.835,409.903 586.613,409.903 ; 581.865,417.91 577.865,417.91 ; 581.866,352.626 583.692,352.626 584.2,352.118 584.2,345.006 583.738,344.544 580.309,344.544 580.263,344.498 ; 582.299,352.193 cw(c583.343,351.149) 583.343,352.626 cw(c583.343,354.104) 582.299,353.059 ; 582.678,385.822 cw(c582.892,385.608) 582.892,385.91 cw(c582.892,386.212) 582.678,385.998 ; 582.678,386.822 cw(c582.892,386.608) 582.892,386.91 cw(c582.892,387.212) 582.678,386.998 ; 582.678,388.822 cw(c582.892,388.608) 582.892,388.91 cw(c582.892,389.212) 582.678,388.998 ; 582.678,389.822 cw(c582.892,389.608) 582.892,389.91 cw(c582.892,390.212) 582.678,389.998 ; 582.678,399.822 cw(c582.892,399.608) 582.892,399.91 cw(c582.892,400.212) 582.678,399.998 ; 582.678,406.822 cw(c582.892,406.608) 582.892,406.91 cw(c582.892,407.212) 582.678,406.998 ; 582.678,407.822 cw(c582.892,407.608) 582.892,407.91 cw(c582.892,408.212) 582.678,407.998 ; 582.777,303.604 582.777,305.94 583.184,306.347 591.347,306.347 593.373,308.373 597.183,308.373 599.116,310.306 599.116,336.751 598.608,337.259 589.915,337.259 589.56,337.614 ; 583.629,378.915 589.661,378.915 590.05,378.526 590.05,356.436 ; 583.629,380.312 589.915,380.312 590.677,379.55 590.677,355.547 ; 583.848,378.734 cw(c584.286,378.296) 584.286,378.915 cw(c584.286,379.534) 583.848,379.096 ; 583.848,380.131 cw(c584.286,379.693) 584.286,380.312 cw(c584.286,380.931) 583.848,380.493 ; 583.896,327.393 ccw(c583.469,327.82) 584.073,327.82 ccw(c584.677,327.82) 584.25,327.393 ; 584.526,399.91 cw(c584.526,399.154) 585.06,399.689 ; v1(584.711,312.243) 586.427,312.243 ; 584.719,399.91 ccw(c584.719,400.392) 585.06,400.051 ; v1@584.852,312.101 cw(c585.194,311.76) 585.194,312.243 cw(c585.194,312.726) v1@584.852,312.384 ; 585.356,327.368 ccw(c584.929,327.795) 585.533,327.795 ccw(c586.137,327.795) 585.71,327.368 ; 585.625,404.505 ccw(c584.857,403.737) 584.857,404.823 ccw(c584.857,405.909) 585.625,405.141 ; 585.625,409.585 ccw(c584.857,408.817) 584.857,409.903 ccw(c584.857,410.989) 585.625,410.221 ; 586.18,311.995 ccw(c585.582,311.398) 585.582,312.243 ccw(c585.582,313.088) 586.18,312.49 ; 586.579,350.277 ccw(c586.135,350.721) 586.763,350.721 ; 586.588,350.286 cw(c587.019,349.855) 587.019,350.465 ; 586.613,407.363 588.391,407.363 588.772,406.982 588.772,400.124 588.518,399.87 586.93,399.87 ; 587.15,399.689 cw(c587.588,399.251) 587.588,399.87 cw(c587.588,400.489) 587.15,400.051 ; 587.261,304.576 ccw(c586.807,305.433) 587.777,305.433 ; 587.402,304.311 ccw(c587.071,304.934) 587.777,304.934 ccw(c588.483,304.934) 588.152,304.311 ; 587.601,407.045 cw(c588.369,406.277) 588.369,407.363 cw(c588.369,408.449) 587.601,407.681 ; v1@587.742,377.758 ccw(c587.4,377.416) 587.4,377.899 ccw(c587.4,378.382) v1@587.742,378.04 ; 587.777,303.604 587.777,305.433 ; 588.293,304.576 cw(c588.747,305.433) 587.777,305.433 ; v1@588.82,390.678 611.632,390.678 612.219,390.678 612.521,390.98 612.521,393.33 ; v1@588.913,390.585 cw(c589.138,390.36) 589.138,390.678 ; v1@588.913,390.867 ccw(c589.372,391.326) 589.372,390.678 ; 589.248,338.169 cw(c588.911,337.614) 589.56,337.614 ; 589.307,332.168 cw(c589.123,331.772) 589.56,331.772 ; v1@589.52,355.66 ccw(c589.178,355.318) 589.178,355.801 ccw(c589.178,356.284) v1@589.52,355.942 ; v1@589.526,355.92 589.534,355.92 590.05,356.436 ; 589.56,332.712 589.56,331.772 ; 589.56,338.681 589.56,337.614 ; v1@589.646,356 ccw(c589.613,356.436) 590.05,356.436 ; v1@589.669,355.701 ccw(c589.638,356.113) 590.05,356.113 ; v1@589.727,355.99 ccw(c589.83,356.283) 590.05,356.063 ; 589.813,332.168 ccw(c589.996,331.772) 589.56,331.772 ; v1@589.858,355.834 cw(c590.536,355.95) 590.05,356.436 ; 589.872,338.169 ccw(c590.209,337.614) 589.56,337.614 ; 590.636,354.277 590.636,354.445 590.169,354.912 590.677,355.42 590.677,355.547 ; 590.677,354.912 590.677,355.547 ; 592.989,335.697 598.092,335.697 ; 592.989,338.681 594.208,338.681 ; 593.413,332.288 cw(c594.437,331.264) 594.437,332.712 cw(c594.437,334.161) 593.413,333.137 ; 593.413,335.273 cw(c594.437,334.248) 594.437,335.697 cw(c594.437,337.145) 593.413,336.121 ; 593.464,338.316 cw(c594.208,337.744) 594.208,338.681 ; 593.464,339.047 ccw(c594.208,339.619) 594.208,338.681 ; v1@593.584,392.518 ccw(c593.242,392.86) 593.725,392.86 ccw(c594.208,392.86) v1@593.866,392.518 ; v1(593.725,392.377) 593.725,403.807 594.289,404.371 596.436,404.371 ; 594.409,393.483 cw(c594.586,393.185) 594.831,393.43 ; v1@594.563,393.225 cw(c594.79,392.844) 595.103,393.158 ; 594.574,393.687 cw(c594.175,393.289) v1@594.709,393.107 ; v1@594.727,332.571 ccw(c594.385,332.23) 594.385,332.712 ccw(c594.385,333.195) v1@594.727,332.854 ; v1@594.73,393.302 cw(c595.067,393.774) 594.487,393.774 ; v1@594.755,392.998 cw(c595.097,392.656) 595.097,393.139 cw(c595.097,393.622) v1@594.755,393.28 ; v1@595.009,332.571 cw(c595.351,332.23) 595.351,332.712 cw(c595.351,333.195) v1@595.009,332.854 ; 595.376,393.139 595.122,393.139 594.487,393.774 ; 595.429,394.844 ccw(c594.991,395.282) 595.611,395.282 ccw(c596.23,395.282) 595.792,394.844 ; v1@595.489,395.411 cw(c595.194,395.116) 595.611,395.116 ; v1@595.489,395.693 ccw(c595.194,395.988) 595.611,395.988 ; 595.611,394.663 595.611,399.945 596.436,400.771 ; 595.611,395.022 cw(c596.16,395.022) v1@595.771,395.411 ; 595.611,396.082 ccw(c596.16,396.082) v1@595.771,395.693 ; 595.768,402.253 ccw(c595,401.485) 595,402.571 ccw(c595,403.657) 595.768,402.889 ; 595.768,404.053 ccw(c595,403.285) 595,404.371 ccw(c595,405.457) 595.768,404.689 ; 596.436,402.571 594.902,402.571 594.487,402.156 594.487,393.774 ; 597.154,335.697 ccw(c597.154,336.31) v1@597.588,335.876 ; 597.262,394.663 599.44,394.663 ; 597.338,335.697 cw(c597.338,335.344) v1@597.588,335.594 ; 597.481,394.482 cw(c597.919,394.044) 597.919,394.663 cw(c597.919,395.282) 597.481,394.844 ; v1@597.844,335.571 cw(c598.027,335.307) 598.254,335.535 ; v1@597.878,335.601 cw(c598.092,335.409) 598.092,335.697 ; v1@597.913,335.815 ccw(c598.092,335.893) 598.092,335.697 ; 598.968,396.203 cw(c598.2,395.435) 599.286,395.435 cw(c600.372,395.435) 599.604,396.203 ; 599.142,308.151 cw(c599.712,308.151) 599.309,308.553 ; 599.186,308.407 ccw(c599.186,309.118) 599.689,308.615 ; 599.286,396.871 599.286,394.817 599.44,394.663 ; 599.319,306.719 ccw(c599.532,307.068) 599.821,306.779 ; 599.334,393.033 ccw(c599.078,392.777) 599.078,393.139 ccw(c599.078,393.501) 599.334,393.245 ; 599.367,306.28 cw(c599.805,305.842) 599.805,306.462 cw(c599.805,307.081) 599.367,306.643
